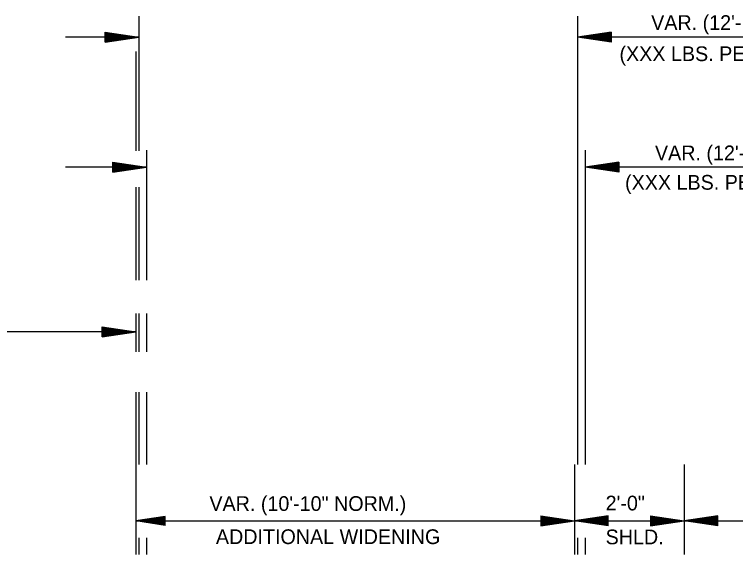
# Model space of a CAD drawing. Extents: x 635488 to 635865, y 290537 to 290973.
# Drawn here: x 635514.88 to 635544.25, y 290837.94 to 290859.93 of the extents above; entities that cross this region are included whole.
import ezdxf

# ---------------------------------------------------------------- set-up
doc = ezdxf.new("R2010")
doc.units = 0
doc.layers.add('Default', color=7, linetype='Continuous')

msp = doc.modelspace()

# ---------------------------------------------------------------- linework, layer by layer
at = {"layer": 'Default'}
for p, q in [((635519.95, 290859.856), (635519.95, 290854.374)), ((635537.821, 290859.856), (635537.821, 290841.602)), ((635519.95, 290859.005), (635516.965, 290859.005)), ((635518.582, 290859.209), (635519.95, 290859.005)), ((635518.582, 290858.799), (635518.582, 290859.209)), ((635518.582, 290859.176), (635519.723, 290859.005)), ((635518.582, 290859.141), (635519.487, 290859.005)), ((635518.582, 290859.108), (635519.258, 290859.005)), ((635518.582, 290859.069), (635519.026, 290859.005)), ((635518.582, 290859.038), (635518.799, 290859.005)), ((635518.582, 290858.799), (635519.95, 290859.005)), ((635518.582, 290858.937), (635519.026, 290859.005)), ((635518.582, 290858.868), (635519.487, 290859.005)), ((635518.582, 290858.834), (635519.723, 290859.005)), ((635518.582, 290858.904), (635519.258, 290859.005)), ((635518.582, 290858.972), (635518.799, 290859.005)), ((635539.191, 290859.209), (635537.821, 290859.005)), ((635539.191, 290858.799), (635537.821, 290859.005)), ((635569.047, 290859.005), (635537.821, 290859.005)), ((635539.191, 290859.176), (635538.048, 290859.005)), ((635539.191, 290858.834), (635538.048, 290859.005)), ((635539.191, 290859.141), (635538.285, 290859.005)), ((635539.191, 290858.868), (635538.285, 290859.005)), ((635539.191, 290859.108), (635538.513, 290859.005)), ((635539.191, 290858.904), (635538.513, 290859.005)), ((635539.191, 290859.069), (635538.745, 290859.005)), ((635539.191, 290858.937), (635538.745, 290859.005)), ((635539.191, 290859.038), (635538.972, 290859.005)), ((635539.191, 290858.972), (635538.972, 290859.005)), ((635539.191, 290859.209), (635539.191, 290858.799)), ((635519.824, 290858.427), (635519.824, 290854.374)), ((635520.257, 290854.402), (635520.257, 290849.116)), ((635538.128, 290854.402), (635538.128, 290841.602)), ((635520.257, 290853.718), (635516.965, 290853.718)), ((635518.889, 290853.922), (635520.257, 290853.718)), ((635518.889, 290853.512), (635518.889, 290853.922)), ((635518.889, 290853.889), (635520.031, 290853.718)), ((635518.889, 290853.853), (635519.796, 290853.718)), ((635518.889, 290853.821), (635519.569, 290853.718)), ((635518.889, 290853.783), (635519.336, 290853.718)), ((635518.889, 290853.75), (635519.107, 290853.718)), ((635518.889, 290853.512), (635520.257, 290853.718)), ((635518.889, 290853.649), (635519.336, 290853.718)), ((635518.889, 290853.581), (635519.796, 290853.718)), ((635518.889, 290853.546), (635520.031, 290853.718)), ((635518.889, 290853.615), (635519.569, 290853.718)), ((635518.889, 290853.687), (635519.107, 290853.718)), ((635539.498, 290853.922), (635538.128, 290853.718)), ((635539.498, 290853.512), (635538.128, 290853.718)), ((635568.697, 290853.718), (635538.128, 290853.718)), ((635539.498, 290853.889), (635538.359, 290853.718)), ((635539.498, 290853.546), (635538.359, 290853.718)), ((635539.498, 290853.853), (635538.592, 290853.718)), ((635539.498, 290853.581), (635538.592, 290853.718)), ((635539.498, 290853.821), (635538.82, 290853.718)), ((635539.498, 290853.615), (635538.82, 290853.718)), ((635539.498, 290853.783), (635539.052, 290853.718)), ((635539.498, 290853.649), (635539.052, 290853.718)), ((635539.498, 290853.75), (635539.281, 290853.718)), ((635539.498, 290853.687), (635539.281, 290853.718)), ((635539.498, 290853.922), (635539.498, 290853.512)), ((635519.824, 290852.897), (635519.824, 290849.116)), ((635519.95, 290852.897), (635519.95, 290849.116)), ((635519.824, 290847.748), (635519.824, 290846.196)), ((635519.95, 290847.748), (635519.95, 290846.196)), ((635520.257, 290847.748), (635520.257, 290846.196)), ((635519.824, 290847.005), (635491.959, 290847.005)), ((635518.454, 290847.209), (635519.824, 290847.005)), ((635518.454, 290846.799), (635518.454, 290847.209)), ((635518.454, 290847.176), (635519.597, 290847.005)), ((635518.454, 290847.14), (635519.36, 290847.005)), ((635518.454, 290847.107), (635519.131, 290847.005)), ((635518.454, 290847.07), (635518.9, 290847.005)), ((635518.454, 290847.037), (635518.672, 290847.005)), ((635518.454, 290846.799), (635519.824, 290847.005)), ((635518.454, 290846.936), (635518.9, 290847.005)), ((635518.454, 290846.867), (635519.36, 290847.005)), ((635518.454, 290846.833), (635519.597, 290847.005)), ((635518.454, 290846.903), (635519.131, 290847.005)), ((635518.454, 290846.972), (635518.672, 290847.005)), ((635519.824, 290844.553), (635519.824, 290837.937)), ((635519.95, 290844.553), (635519.95, 290841.602)), ((635520.257, 290844.553), (635520.257, 290841.602)), ((635537.693, 290841.602), (635537.693, 290837.937)), ((635542.16, 290841.602), (635542.16, 290837.937)), ((635521.024, 290839.487), (635519.824, 290839.307)), ((635519.824, 290839.307), (635537.693, 290839.307)), ((635521.024, 290839.127), (635519.824, 290839.307)), ((635521.024, 290839.457), (635520.024, 290839.307)), ((635521.024, 290839.157), (635520.024, 290839.307)), ((635521.024, 290839.426), (635520.231, 290839.307)), ((635521.024, 290839.188), (635520.231, 290839.307)), ((635521.024, 290839.396), (635520.431, 290839.307)), ((635521.024, 290839.218), (635520.431, 290839.307)), ((635521.024, 290839.366), (635520.634, 290839.307)), ((635521.024, 290839.249), (635520.634, 290839.307)), ((635521.024, 290839.335), (635520.834, 290839.307)), ((635521.024, 290839.279), (635520.834, 290839.307)), ((635521.024, 290839.127), (635521.024, 290839.487)), ((635536.325, 290839.511), (635537.693, 290839.307)), ((635536.325, 290839.511), (635536.325, 290839.101)), ((635536.325, 290839.478), (635537.464, 290839.307)), ((635536.325, 290839.442), (635537.23, 290839.307)), ((635536.325, 290839.409), (635537.003, 290839.307)), ((635536.325, 290839.372), (635536.767, 290839.307)), ((635536.325, 290839.339), (635536.54, 290839.307)), ((635536.325, 290839.101), (635537.693, 290839.307)), ((635536.325, 290839.238), (635536.767, 290839.307)), ((635536.325, 290839.169), (635537.23, 290839.307)), ((635536.325, 290839.135), (635537.464, 290839.307)), ((635536.325, 290839.205), (635537.003, 290839.307)), ((635536.325, 290839.274), (635536.54, 290839.307)), ((635539.063, 290839.511), (635537.693, 290839.307)), ((635537.693, 290839.307), (635542.16, 290839.307)), ((635539.063, 290839.101), (635537.693, 290839.307)), ((635539.063, 290839.478), (635537.921, 290839.307)), ((635539.063, 290839.135), (635537.921, 290839.307)), ((635539.063, 290839.442), (635538.156, 290839.307)), ((635539.063, 290839.169), (635538.156, 290839.307)), ((635539.063, 290839.409), (635538.385, 290839.307)), ((635539.063, 290839.205), (635538.385, 290839.307)), ((635539.063, 290839.372), (635538.616, 290839.307)), ((635539.063, 290839.238), (635538.616, 290839.307)), ((635539.063, 290839.339), (635538.843, 290839.307)), ((635539.063, 290839.274), (635538.843, 290839.307)), ((635539.063, 290839.101), (635539.063, 290839.511)), ((635540.792, 290839.511), (635542.16, 290839.307)), ((635540.792, 290839.511), (635540.792, 290839.101)), ((635540.792, 290839.478), (635541.931, 290839.307)), ((635540.792, 290839.442), (635541.697, 290839.307)), ((635540.792, 290839.409), (635541.47, 290839.307)), ((635540.792, 290839.372), (635541.234, 290839.307)), ((635540.792, 290839.339), (635541.007, 290839.307)), ((635540.792, 290839.101), (635542.16, 290839.307)), ((635540.792, 290839.238), (635541.234, 290839.307)), ((635540.792, 290839.169), (635541.697, 290839.307)), ((635540.792, 290839.135), (635541.931, 290839.307)), ((635540.792, 290839.205), (635541.47, 290839.307)), ((635540.792, 290839.274), (635541.007, 290839.307)), ((635543.53, 290839.511), (635542.16, 290839.307)), ((635542.16, 290839.307), (635551.153, 290839.307)), ((635543.53, 290839.101), (635542.16, 290839.307)), ((635543.53, 290839.478), (635542.388, 290839.307)), ((635543.53, 290839.135), (635542.388, 290839.307)), ((635543.53, 290839.442), (635542.623, 290839.307)), ((635543.53, 290839.169), (635542.623, 290839.307)), ((635543.53, 290839.409), (635542.852, 290839.307)), ((635543.53, 290839.205), (635542.852, 290839.307)), ((635543.53, 290839.372), (635543.083, 290839.307)), ((635543.53, 290839.238), (635543.083, 290839.307)), ((635543.53, 290839.339), (635543.31, 290839.307)), ((635543.53, 290839.274), (635543.31, 290839.307)), ((635543.53, 290839.101), (635543.53, 290839.511)), ((635519.95, 290838.623), (635519.95, 290837.937)), ((635520.257, 290838.623), (635520.257, 290837.937)), ((635537.693, 290838.623), (635537.693, 290837.937)), ((635537.821, 290838.623), (635537.821, 290837.937)), ((635538.128, 290838.623), (635538.128, 290837.937))]:
    msp.add_line(p, q, dxfattribs=at)

# ---------------------------------------------------------------- texts
for s, p in [('VAR. (12\'-10" NORM.) ACHM SURFACE COURSE (1/2")', (635540.815, 290859.302)), ('(XXX LBS. PER SQ. YD.) & TACK COAT', (635539.525, 290858.032)), ('VAR. (12\'-10" NORM.) ACHM BINDER COURSE (1")', (635540.97, 290853.995)), ('(XXX LBS. PER SQ. YD.) & TACK COAT', (635539.753, 290852.795)), ('VAR. (10\'-10" NORM.)', (635522.825, 290839.715)), ('2\'-0"', (635538.96, 290839.735)), ('ADDITIONAL WIDENING', (635523.09, 290838.365)), ('SHLD.', (635538.96, 290838.356))]:
    msp.add_text(s, height=0.6, dxfattribs=at).set_placement(p)

doc.saveas('drawing.dxf')
